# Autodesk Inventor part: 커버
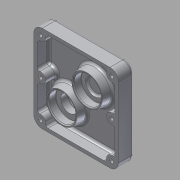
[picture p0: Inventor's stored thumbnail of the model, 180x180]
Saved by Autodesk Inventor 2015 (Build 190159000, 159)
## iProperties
Created: 2015-10
Part Number: 커버
Material: 알루미늄 6061
Document SubType Name: Modeling
Designer: mduedu
Density: 2.71 g/cm^3
Mass: 254.004 g
Surface Area: 401.286 cm^2
Volume: 93.7286 cm^3
Appearance: 알루미늄 - 평지
Author: mduedu
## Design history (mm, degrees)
sketch "스케치1"
  geometry: L1 (-50, -51.5)-(50, -51.5); L2 (50, -51.5)-(50, 51.5); L3 (50, 51.5)-(-50, 51.5); L4 (-50, 51.5)-(-50, -51.5); L5 (-50, -51.5)-(50, 51.5); L6 (50, -51.5)-(-50, 51.5); 1 further point
  constraints: 12 end point, 2 midpoint, 2 parallel, 1 horizontal, 1 perpendicular
  dimensions: "d0" = 100 distance of L3.end L2.end; "d1" = 103 distance of L2.end L1.end
extrude "돌출1" new body sketch "스케치1" distance "d2" = 18; taper "d3" = 0 deg
fillet "모깎기1" dims "d4" = 10
fillet "모깎기2" dims "d5" = 3
feature "쉘1" dims "d6" = 4
sketch "스케치2"
  geometry: L1 (40, 51.5)-(-40, 51.5) reference; L2 (50, -41.5)-(50, 41.5) reference; L3 (-40, -51.5)-(40, -51.5) reference; L4 (-50, 41.5)-(-50, -41.5) reference; L5 (-50, 0)-(50, 0); L6 (0, 51.5)-(0, -51.5); C1 r 6 at (-42, 43.5); C2 r 6 at (-42, 0); C3 r 6 at (-42, -43.5); C4 r 6 at (42, -43.5); C5 r 6 at (42, 0); C6 r 6 at (42, 43.5); 1 further point
  constraints: 6 centre point, 4 end point, 4 midpoint, 4 symmetric about line, 1 equal radius, 1 point on line, 1 vertical alignment, 4 other
  dimensions: "d7" = 12 diameter of C1; "d8" = 8 distance from line of C1.centre L1; "d9" = 8 distance from line of C1.centre L4
extrude "돌출2" join sketch "스케치2" stored distance "d10" = 0; taper "d11" = 0 deg
fillet "모깎기3" dims "d12" = 3
fillet "모깎기4" dims "d13" = 3
sketch "스케치3"
  geometry: A1 r 6 centre (42, 43.5) between (36.037, 44.167) and (42.667, 37.537) reference; A2 r 6 centre (42, 0) between (42.667, 5.963) and (42.667, -5.963) reference; A3 r 6 centre (42, -43.5) between (42.667, -37.537) and (36.037, -44.167) reference; A4 r 6 centre (-42, -43.5) between (-36.037, -44.167) and (-42.667, -37.537) reference; A5 r 6 centre (-42, 0) between (-42.667, -5.963) and (-42.667, 5.963) reference; A6 r 6 centre (-42, 43.5) between (-42.667, 37.537) and (-36.037, 44.167) reference; 7 further points
  constraints: 6 coincident
hole "구멍1" sketch "스케치3" at (-42, 43.5), (-42, 0), (-42, -43.5), (42, -43.5), (42, 0), (42, 43.5) diameter "d14" = 4.5; stored, may be unused: countersink angle "d18" = 90 deg, drill point angle "d20" = 118 deg; dims "d15" = 6, "d16" = 8, "d17" = 4.4, "d19" = 8
sketch "스케치4"
  geometry: L1 (83.056, 3)-(83.056, 86) reference; L2 (73.056, 96)-(-6.944, 96) reference; C1 r 20 at (43.056, 56); 1 further point
  constraints: 1 centre point
  dimensions: "d21" = 40 diameter of C1; "d22" = 40 distance from line of C1.centre L1; "d23" = 40 distance from line of C1.centre L2
extrude "돌출3" join sketch "스케치4" distance "d24" = 11; taper "d25" = -10 deg
hole "구멍2" diameter "d28" = 22; stored, may be unused: countersink angle "d32" = 90 deg, drill point angle "d34" = 0 deg; dims "d29" = 6, "d30" = 32, "d31" = 9, "d33" = 11, "d35" = 10, "d36" = 10
sketch "스케치5"
  geometry: L1 (-40, -51.5)-(40, -51.5) reference; L2 (50, -41.5)-(50, 41.5) reference; C1 r 25 at (20, -21.5); 1 further point
  constraints: 1 centre point
  dimensions: "d37" = 50 diameter of C1; "d40" = 30 distance from line of C1.centre L1; "d41" = 30 distance from line of C1.centre L2
extrude "돌출4" join sketch "스케치5" distance "d42" = 15; taper "d43" = -10 deg
sketch "스케치6"
  geometry: C1 r 25 at (13.056, 23) reference; C2 r 20 at (13.056, 23); 1 further point
  constraints: 1 centre point, 1 coincident
  dimensions: "d44" = 40 diameter of C2
extrude "돌출5" join sketch "스케치6" distance "d45" = 11; taper "d46" = -10 deg
hole "구멍3" diameter "d49" = 20; stored, may be unused: countersink angle "d53" = 90 deg, drill point angle "d55" = 118 deg; dims "d47" = 10, "d48" = 10, "d50" = 6, "d51" = 32, "d52" = 9, "d54" = 11
hole "구멍4" diameter "d58" = 24; stored, may be unused: countersink angle "d62" = 90 deg, drill point angle "d64" = 0 deg; dims "d56" = 10, "d57" = 10, "d59" = 6, "d60" = 28, "d61" = 11, "d63" = 13
chamfer "모따기1" distance "d65" = 1; stored, may be unused: second distance "d66" = 2, angle "d67" = 45 deg
sketch "스케치7" dims "d68" = 36
  geometry: C1 r 25 at (0, 0) reference; 3 further points
  constraints: 2 vertical alignment, 1 coincident, 2 other
hole "구멍5" sketch "스케치7" at (0, 18) diameter "d69" = 2.459; stored, may be unused: countersink angle "d73" = 90 deg, drill point angle "d75" = 118 deg; dims "d70" = 8, "d71" = 28, "d72" = 11, "d74" = 10
sketch "스케치8"
  geometry: L1 (-50, 41.5)-(-50, -41.5) reference; L2 (40, 51.5)-(-40, 51.5) reference; 2 further points
  constraints: 1 other
  dimensions: "d79" = 50 distance from line of point (0, 26.5) L1; "d80" = 25 distance from line of point (0, 26.5) L2
feature "엠보싱1" sketch "스케치8" dims "d0" = 100, "d1" = 103, "d5" = 3, "d81" = 0.5, "d82" = 0
fillet "모깎기5" dims "d83" = 3
fillet "모깎기6" dims "d84" = 3
fillet "모깎기7" dims "d85" = 3
fillet "모깎기8" dims "d86" = 0.3
fillet "모깎기9" dims "d87" = 3
node "솔리드1"
pattern_circular "원형 패턴1" dims angle "d77" = 360 deg
